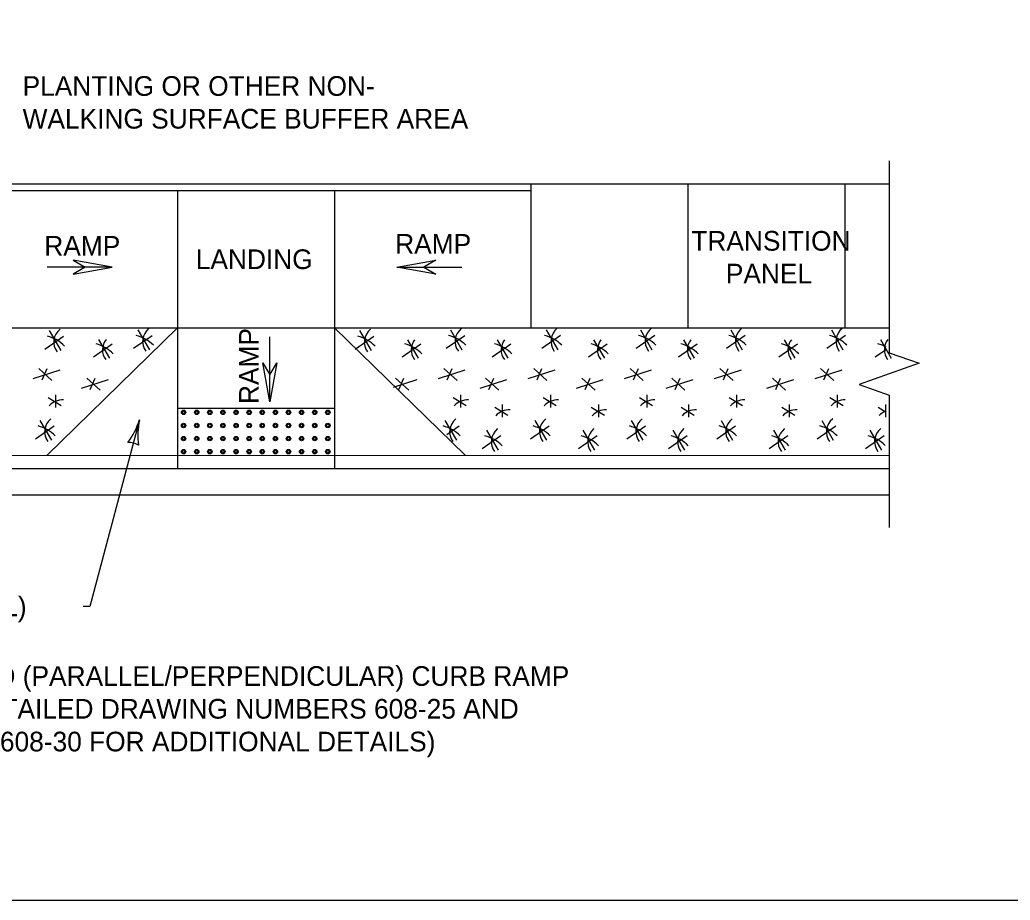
# Model space of a CAD drawing. Extents: x 49991.4 to 50021, y 49987.6 to 50011.4.
# Drawn here: x 50011.508 to 50014.53, y 49999.886 to 50002.573 of the extents above; entities that cross this region are included whole.
import ezdxf

# ---------------------------------------------------------------- set-up
doc = ezdxf.new("R2010")
doc.units = 0
for name, color, linetype in [('Level 1', 7, 'Continuous'), ('Level 2', 7, 'Continuous'), ('Level 3', 7, 'Continuous'), ('Level 6', 7, 'Continuous')]:
    doc.layers.add(name, color=color, linetype=linetype)

msp = doc.modelspace()

# ---------------------------------------------------------------- linework, layer by layer
at = {"layer": 'Level 1'}
for p, q in [((50010.2316, 50002.0716), (50014.16, 50002.0715)), ((50013.0671, 50002.0715), (50013.067, 50001.6325)), ((50013.5463, 50002.0714), (50013.5461, 50001.6326)), ((50014.0255, 50002.0712), (50014.0253, 50001.6324)), ((50011.3901, 50002.0515), (50013.0671, 50002.0516)), ((50011.9889, 50002.0515), (50011.989, 50001.2031)), ((50012.4681, 50002.0515), (50012.4682, 50001.2031)), ((50010.2317, 50001.6321), (50014.16, 50001.6325)), ((50011.5841, 50001.5677), (50011.6411, 50001.6073)), ((50011.989, 50001.6323), (50011.59, 50001.2432)), ((50011.5974, 50001.6241), (50011.6327, 50001.5631)), ((50011.6154, 50001.6323), (50011.6155, 50001.6321)), ((50011.6261, 50001.6321), (50011.6263, 50001.6323)), ((50011.8551, 50001.57), (50011.9121, 50001.6096)), ((50011.8685, 50001.6264), (50011.9037, 50001.5654)), ((50011.9094, 50001.6323), (50011.9095, 50001.6321)), ((50011.9201, 50001.6321), (50011.9203, 50001.6323)), ((50012.4682, 50001.6323), (50012.867, 50001.2434)), ((50012.5313, 50001.5675), (50012.5884, 50001.6071)), ((50012.5447, 50001.6239), (50012.58, 50001.5629)), ((50012.8083, 50001.57), (50012.8653, 50001.6096)), ((50012.8216, 50001.6264), (50012.8569, 50001.5654)), ((50013.101, 50001.5702), (50013.158, 50001.6098)), ((50013.1143, 50001.6265), (50013.1496, 50001.5656)), ((50013.3881, 50001.5702), (50013.4451, 50001.6098)), ((50013.4014, 50001.6265), (50013.4367, 50001.5656)), ((50013.6637, 50001.5702), (50013.7207, 50001.6098)), ((50013.677, 50001.6265), (50013.7123, 50001.5656)), ((50013.9706, 50001.5702), (50014.0276, 50001.6098)), ((50013.9839, 50001.6265), (50014.0192, 50001.5656)), ((50011.7326, 50001.5443), (50011.7897, 50001.5839)), ((50011.7481, 50001.5969), (50011.7812, 50001.5396)), ((50012.6744, 50001.5443), (50012.7315, 50001.5839)), ((50012.6903, 50001.5963), (50012.7231, 50001.5396)), ((50012.9487, 50001.5443), (50013.0058, 50001.5839)), ((50012.9646, 50001.5963), (50012.9974, 50001.5396)), ((50013.2427, 50001.5443), (50013.2998, 50001.5839)), ((50013.2586, 50001.5963), (50013.2914, 50001.5396)), ((50013.5171, 50001.5443), (50013.5741, 50001.5839)), ((50013.5329, 50001.5963), (50013.5657, 50001.5396)), ((50013.824, 50001.5443), (50013.881, 50001.5839)), ((50013.8398, 50001.5963), (50013.8726, 50001.5396)), ((50014.1338, 50001.5964), (50014.1666, 50001.5397)), ((50014.118, 50001.5444), (50014.1518, 50001.5678)), ((50011.5491, 50001.4783), (50011.6312, 50001.5043)), ((50011.6061, 50001.4722), (50011.5658, 50001.5088)), ((50011.5759, 50001.4738), (50011.591, 50001.5088)), ((50012.7849, 50001.4783), (50012.867, 50001.5043)), ((50012.8419, 50001.4722), (50012.8016, 50001.5088)), ((50012.8117, 50001.4738), (50012.8268, 50001.5088)), ((50013.0592, 50001.4783), (50013.1414, 50001.5043)), ((50013.1162, 50001.4722), (50013.0759, 50001.5088)), ((50013.0861, 50001.4738), (50013.1011, 50001.5088)), ((50013.3532, 50001.4783), (50013.4354, 50001.5043)), ((50013.4102, 50001.4722), (50013.3699, 50001.5088)), ((50013.3801, 50001.4738), (50013.3951, 50001.5088)), ((50013.6275, 50001.4783), (50013.7097, 50001.5043)), ((50013.6846, 50001.4722), (50013.6442, 50001.5088)), ((50013.6544, 50001.4738), (50013.6695, 50001.5088)), ((50013.9344, 50001.4783), (50014.0166, 50001.5043)), ((50013.9915, 50001.4722), (50013.9511, 50001.5088)), ((50013.9613, 50001.4738), (50013.9764, 50001.5088)), ((50011.6959, 50001.4483), (50011.7781, 50001.4743)), ((50011.753, 50001.4422), (50011.7126, 50001.4788)), ((50011.7228, 50001.4438), (50011.7379, 50001.4788)), ((50012.6485, 50001.4517), (50012.7199, 50001.4743)), ((50012.6948, 50001.4422), (50012.6544, 50001.4788)), ((50012.6646, 50001.4438), (50012.6797, 50001.4788)), ((50012.9121, 50001.4483), (50012.9942, 50001.4743)), ((50012.9691, 50001.4422), (50012.9288, 50001.4788)), ((50012.9389, 50001.4438), (50012.954, 50001.4788)), ((50013.2061, 50001.4483), (50013.2882, 50001.4743)), ((50013.2631, 50001.4422), (50013.2228, 50001.4788)), ((50013.2329, 50001.4438), (50013.248, 50001.4788)), ((50013.4804, 50001.4483), (50013.5626, 50001.4743)), ((50013.5374, 50001.4422), (50013.4971, 50001.4788)), ((50013.5072, 50001.4438), (50013.5223, 50001.4788)), ((50013.7873, 50001.4483), (50013.8695, 50001.4743)), ((50013.8443, 50001.4422), (50013.804, 50001.4788)), ((50013.8141, 50001.4438), (50013.8292, 50001.4788)), ((50014.1232, 50001.4787), (50014.1232, 50001.4789)), ((50011.6175, 50001.3898), (50011.6175, 50001.428)), ((50012.8534, 50001.3898), (50012.8534, 50001.428)), ((50013.1277, 50001.3898), (50013.1277, 50001.428)), ((50013.4217, 50001.3898), (50013.4217, 50001.428)), ((50013.696, 50001.3898), (50013.696, 50001.428)), ((50014.0029, 50001.3898), (50014.0029, 50001.428)), ((50011.5942, 50001.4203), (50011.6344, 50001.3959)), ((50012.83, 50001.4203), (50012.8702, 50001.3959)), ((50012.9805, 50001.3598), (50012.9805, 50001.398)), ((50013.1043, 50001.4203), (50013.1445, 50001.3959)), ((50013.2745, 50001.3598), (50013.2745, 50001.398)), ((50013.3983, 50001.4203), (50013.4385, 50001.3959)), ((50013.5489, 50001.3598), (50013.5489, 50001.398)), ((50013.6726, 50001.4203), (50013.7128, 50001.3959)), ((50013.8558, 50001.3598), (50013.8558, 50001.398)), ((50013.9795, 50001.4203), (50014.0197, 50001.3959)), ((50014.1498, 50001.3599), (50014.1498, 50001.3981)), ((50011.989, 50001.3872), (50012.4682, 50001.3873)), ((50012.9572, 50001.3903), (50012.9974, 50001.3659)), ((50013.2512, 50001.3903), (50013.2914, 50001.3659)), ((50013.5255, 50001.3903), (50013.5657, 50001.3659)), ((50013.8324, 50001.3903), (50013.8726, 50001.3659)), ((50014.1264, 50001.3904), (50014.1515, 50001.3752)), ((50011.5691, 50001.3501), (50011.6044, 50001.2892)), ((50012.8049, 50001.3501), (50012.8402, 50001.2892)), ((50013.0792, 50001.3501), (50013.1145, 50001.2892)), ((50013.3732, 50001.3501), (50013.4085, 50001.2892)), ((50013.6476, 50001.3501), (50013.6828, 50001.2892)), ((50013.9545, 50001.3501), (50013.9897, 50001.2892)), ((50011.5557, 50001.2938), (50011.6128, 50001.3334)), ((50012.8108, 50001.3071), (50012.8486, 50001.3334)), ((50012.9321, 50001.3201), (50012.9674, 50001.2592)), ((50013.0659, 50001.2938), (50013.1229, 50001.3334)), ((50013.2261, 50001.3201), (50013.2614, 50001.2592)), ((50013.3599, 50001.2938), (50013.4169, 50001.3334)), ((50013.5004, 50001.3201), (50013.5357, 50001.2592)), ((50013.6342, 50001.2938), (50013.6912, 50001.3334)), ((50013.8073, 50001.3201), (50013.8426, 50001.2592)), ((50013.9411, 50001.2938), (50013.9981, 50001.3334)), ((50014.1013, 50001.3202), (50014.1366, 50001.2593)), ((50012.9187, 50001.2638), (50012.9758, 50001.3034)), ((50013.2127, 50001.2638), (50013.2698, 50001.3034)), ((50013.4871, 50001.2638), (50013.5441, 50001.3034)), ((50013.794, 50001.2638), (50013.851, 50001.3034)), ((50014.088, 50001.2639), (50014.145, 50001.3035)), ((50010.2316, 50001.243), (50014.16, 50001.2435)), ((50010.2316, 50001.2033), (50014.16, 50001.2029)), ((50010.2316, 50001.1232), (50014.16, 50001.1232))]:
    msp.add_line(p, q, dxfattribs=at)
msp.add_lwpolyline([(50020.9378, 50008.1646), (50009.7374, 50008.1646), (50009.7374, 49999.8856), (50020.9378, 49999.8856)], close=True, dxfattribs=at)
msp.add_lwpolyline([(50020.9378, 50008.1646), (50009.7374, 50008.1646), (50009.7374, 49999.8856), (50020.9378, 49999.8856)], close=True, dxfattribs=at)
for centre, radius in [((50012.0077, 50001.3745), 0.00675), ((50012.0077, 50001.3745), 0.00375), ((50012.0477, 50001.3745), 0.00675), ((50012.0477, 50001.3745), 0.00375), ((50012.0877, 50001.3745), 0.00675), ((50012.0877, 50001.3745), 0.00375), ((50012.1277, 50001.3745), 0.00675), ((50012.1277, 50001.3745), 0.00375), ((50012.1677, 50001.3745), 0.00675), ((50012.1677, 50001.3745), 0.00375), ((50012.2077, 50001.3745), 0.00675), ((50012.2077, 50001.3745), 0.00375), ((50012.2477, 50001.3745), 0.00675), ((50012.2477, 50001.3745), 0.00375), ((50012.2877, 50001.3745), 0.00675), ((50012.2877, 50001.3745), 0.00375), ((50012.3277, 50001.3745), 0.00675), ((50012.3277, 50001.3745), 0.00375), ((50012.3677, 50001.3745), 0.00675), ((50012.3677, 50001.3745), 0.00375), ((50012.4077, 50001.3745), 0.00675), ((50012.4077, 50001.3745), 0.00375), ((50012.4477, 50001.3745), 0.00675), ((50012.4477, 50001.3745), 0.00375), ((50012.0077, 50001.3345), 0.00675), ((50012.0077, 50001.3345), 0.00375), ((50012.0477, 50001.3345), 0.00675), ((50012.0477, 50001.3345), 0.00375), ((50012.0877, 50001.3345), 0.00675), ((50012.0877, 50001.3345), 0.00375), ((50012.1277, 50001.3345), 0.00675), ((50012.1277, 50001.3345), 0.00375), ((50012.1677, 50001.3345), 0.00675), ((50012.1677, 50001.3345), 0.00375), ((50012.2077, 50001.3345), 0.00675), ((50012.2077, 50001.3345), 0.00375), ((50012.2477, 50001.3345), 0.00675), ((50012.2477, 50001.3345), 0.00375), ((50012.2877, 50001.3345), 0.00675), ((50012.2877, 50001.3345), 0.00375), ((50012.3277, 50001.3345), 0.00675), ((50012.3277, 50001.3345), 0.00375), ((50012.3677, 50001.3345), 0.00675), ((50012.3677, 50001.3345), 0.00375), ((50012.4077, 50001.3345), 0.00675), ((50012.4077, 50001.3345), 0.00375), ((50012.4477, 50001.3345), 0.00675), ((50012.4477, 50001.3345), 0.00375), ((50012.0077, 50001.2945), 0.00675), ((50012.0077, 50001.2945), 0.00375), ((50012.0477, 50001.2945), 0.00675), ((50012.0477, 50001.2945), 0.00375), ((50012.0877, 50001.2945), 0.00675), ((50012.0877, 50001.2945), 0.00375), ((50012.1277, 50001.2945), 0.00675), ((50012.1277, 50001.2945), 0.00375), ((50012.1677, 50001.2945), 0.00675), ((50012.1677, 50001.2945), 0.00375), ((50012.2077, 50001.2945), 0.00675), ((50012.2077, 50001.2945), 0.00375), ((50012.2477, 50001.2945), 0.00675), ((50012.2477, 50001.2945), 0.00375), ((50012.2877, 50001.2945), 0.00675), ((50012.2877, 50001.2945), 0.00375), ((50012.3277, 50001.2945), 0.00675), ((50012.3277, 50001.2945), 0.00375), ((50012.3677, 50001.2945), 0.00675), ((50012.3677, 50001.2945), 0.00375), ((50012.4077, 50001.2945), 0.00675), ((50012.4077, 50001.2945), 0.00375), ((50012.4477, 50001.2945), 0.00675), ((50012.4477, 50001.2945), 0.00375), ((50012.0077, 50001.2545), 0.00675), ((50012.0077, 50001.2545), 0.00375), ((50012.0477, 50001.2545), 0.00675), ((50012.0477, 50001.2545), 0.00375), ((50012.0877, 50001.2545), 0.00675), ((50012.0877, 50001.2545), 0.00375), ((50012.1277, 50001.2545), 0.00675), ((50012.1277, 50001.2545), 0.00375), ((50012.1677, 50001.2545), 0.00675), ((50012.1677, 50001.2545), 0.00375), ((50012.2077, 50001.2545), 0.00675), ((50012.2077, 50001.2545), 0.00375), ((50012.2477, 50001.2545), 0.00675), ((50012.2477, 50001.2545), 0.00375), ((50012.2877, 50001.2545), 0.00675), ((50012.2877, 50001.2545), 0.00375), ((50012.3277, 50001.2545), 0.00675), ((50012.3277, 50001.2545), 0.00375), ((50012.3677, 50001.2545), 0.00675), ((50012.3677, 50001.2545), 0.00375), ((50012.4077, 50001.2545), 0.00675), ((50012.4077, 50001.2545), 0.00375), ((50012.4477, 50001.2545), 0.00675), ((50012.4477, 50001.2545), 0.00375)]:
    msp.add_circle(centre, radius, dxfattribs=at)
for centre, major_axis, start_param, end_param in [((50011.6708, 50001.589), (-0.0591, 0), 5.450961, 6.875887), ((50011.6725, 50001.6255), (-0.0591, 0), 6.155919, 6.158231), ((50011.5651, 50001.5492), (0.1074, 0), 1.015046, 1.017455), ((50011.8193, 50001.5955), (-0.0591, 0), 5.527296, 5.530814), ((50011.8344, 50001.5151), (0.1074, 0), 0.715682, 1.301104), ((50011.9418, 50001.5913), (-0.0591, 0), 5.450961, 6.875887), ((50011.9665, 50001.6255), (-0.0591, 0), 6.155426, 6.158231), ((50011.8591, 50001.5492), (0.1074, 0), 1.015046, 1.017966), ((50012.6181, 50001.5889), (-0.0591, 0), 5.450961, 6.875887), ((50012.7876, 50001.5151), (0.1074, 0), 0.715682, 1.301104), ((50012.895, 50001.5913), (-0.0591, 0), 5.450961, 6.875887), ((50013.0803, 50001.5152), (0.1074, 0), 0.715682, 1.301104), ((50013.1877, 50001.5915), (-0.0591, 0), 5.450961, 6.875887), ((50013.3674, 50001.5152), (0.1074, 0), 0.715682, 1.301104), ((50013.4748, 50001.5915), (-0.0591, 0), 5.450961, 6.875887), ((50013.643, 50001.5152), (0.1074, 0), 0.715682, 1.301104), ((50013.7504, 50001.5915), (-0.0591, 0), 5.450961, 6.875887), ((50013.9499, 50001.5152), (0.1074, 0), 0.715682, 1.301104), ((50014.0573, 50001.5915), (-0.0591, 0), 5.450961, 6.875887), ((50011.5634, 50001.5128), (0.1074, 0), 0.715682, 1.301104), ((50011.712, 50001.4893), (0.1074, 0), 0.715682, 1.301104), ((50011.8193, 50001.5656), (-0.0591, 0), 5.660038, 6.875887), ((50012.5107, 50001.5126), (0.1074, 0), 0.715682, 1.301104), ((50012.6538, 50001.4893), (0.1074, 0), 0.715682, 1.301104), ((50012.7611, 50001.5656), (-0.0591, 0), 5.673488, 6.875887), ((50012.9281, 50001.4893), (0.1074, 0), 0.715682, 1.301104), ((50013.0355, 50001.5656), (-0.0591, 0), 5.673488, 6.875887), ((50013.2221, 50001.4893), (0.1074, 0), 0.715682, 1.301104), ((50013.3295, 50001.5656), (-0.0591, 0), 5.673488, 6.875887), ((50013.4964, 50001.4893), (0.1074, 0), 0.715682, 1.301104), ((50013.6038, 50001.5656), (-0.0591, 0), 5.673488, 6.875887), ((50013.8033, 50001.4893), (0.1074, 0), 0.715682, 1.301104), ((50013.9107, 50001.5656), (-0.0591, 0), 5.673488, 6.875887), ((50014.0973, 50001.4894), (0.1074, 0), 1.043909, 1.301104), ((50014.2047, 50001.5657), (-0.0591, 0), 5.673488, 6.875887), ((50011.6411, 50001.3606), (-0.0573, 0), 4.712389, 5.577205), ((50012.8769, 50001.3606), (-0.0573, 0), 4.712389, 5.577205), ((50013.1512, 50001.3606), (-0.0573, 0), 4.712389, 5.577205), ((50013.4452, 50001.3606), (-0.0573, 0), 4.712389, 5.577205), ((50013.7196, 50001.3606), (-0.0573, 0), 4.712389, 5.577205), ((50014.0265, 50001.3606), (-0.0573, 0), 4.712389, 5.577205), ((50013.0041, 50001.3306), (-0.0573, 0), 4.712389, 5.577205), ((50013.2981, 50001.3306), (-0.0573, 0), 4.712389, 5.577205), ((50013.5724, 50001.3306), (-0.0573, 0), 4.712389, 5.577205), ((50013.8793, 50001.3306), (-0.0573, 0), 4.712389, 5.577205), ((50014.1733, 50001.3307), (-0.0573, 0), 5.123504, 5.577205), ((50011.6425, 50001.3151), (-0.0591, 0), 5.450961, 6.875887), ((50012.8783, 50001.3151), (-0.0591, 0), 5.450961, 6.875887), ((50013.1526, 50001.3151), (-0.0591, 0), 5.450961, 6.875887), ((50013.4466, 50001.3151), (-0.0591, 0), 5.450961, 6.875887), ((50013.7209, 50001.3151), (-0.0591, 0), 5.450961, 6.875887), ((50014.0278, 50001.3151), (-0.0591, 0), 5.450961, 6.875887), ((50011.5351, 50001.2388), (0.1074, 0), 0.715682, 1.301104), ((50012.7709, 50001.2388), (0.1074, 0), 0.715682, 1.301104), ((50013.0055, 50001.2851), (-0.0591, 0), 5.450961, 6.875887), ((50013.0452, 50001.2388), (0.1074, 0), 0.715682, 1.301104), ((50013.2995, 50001.2851), (-0.0591, 0), 5.450961, 6.875887), ((50013.3392, 50001.2388), (0.1074, 0), 0.715682, 1.301104), ((50013.5738, 50001.2851), (-0.0591, 0), 5.450961, 6.875887), ((50013.6135, 50001.2388), (0.1074, 0), 0.715682, 1.301104), ((50013.8807, 50001.2851), (-0.0591, 0), 5.450961, 6.875887), ((50013.9204, 50001.2388), (0.1074, 0), 0.715682, 1.301104), ((50014.1747, 50001.2852), (-0.0591, 0), 5.450961, 6.875887), ((50012.8981, 50001.2088), (0.1074, 0), 0.715682, 1.301104), ((50013.1921, 50001.2088), (0.1074, 0), 0.715682, 1.301104), ((50013.4664, 50001.2088), (0.1074, 0), 0.715682, 1.301104), ((50013.7733, 50001.2088), (0.1074, 0), 0.715682, 1.301104), ((50014.0673, 50001.2089), (0.1074, 0), 0.715682, 1.301104)]:
    msp.add_ellipse(centre, major_axis=major_axis, ratio=0.909091, start_param=start_param, end_param=end_param, dxfattribs=at)
at = {"layer": 'Level 3'}
for p, q in [((50011.7902, 50001.8175), (50011.5916, 50001.8175)), ((50012.6583, 50001.8175), (50012.857, 50001.8175)), ((50012.2709, 50001.4065), (50012.2709, 50001.6052)), ((50011.8732, 50001.3517), (50011.722, 50000.782)), ((50011.722, 50000.782), (50011.7016, 50000.782))]:
    msp.add_line(p, q, dxfattribs=at)
for points in [[(50011.6711, 50001.7967), (50011.7902, 50001.8175), (50011.6711, 50001.8387), (50011.7074, 50001.8176)], [(50012.7774, 50001.7967), (50012.6583, 50001.8175), (50012.7774, 50001.8387), (50012.7411, 50001.8176)], [(50012.2917, 50001.5257), (50012.2709, 50001.4065), (50012.2496, 50001.5257), (50012.2707, 50001.4893)]]:
    msp.add_lwpolyline(points, close=True, dxfattribs=at)
for centre, radius, start, end in [((50011.6608, 50001.4176), 0.2223, 322.5901, 342.7736), ((50012.1011, 50001.3032), 0.233, 167.9614, 187.2112), ((50011.8403, 50001.2278), 0.0548, 57.2729, 92.9952)]:
    msp.add_arc(centre, radius, start, end, dxfattribs=at)
at = {"layer": 'Level 6'}
for p, q in [((50014.16, 50002.1417), (50014.16, 50001.5566)), ((50014.16, 50001.5566), (50014.2514, 50001.5242)), ((50014.2514, 50001.5242), (50014.16, 50001.4918)), ((50014.16, 50001.4918), (50014.0686, 50001.4594)), ((50014.0686, 50001.4594), (50014.16, 50001.427)), ((50014.16, 50001.427), (50014.16, 50001.0233))]:
    msp.add_line(p, q, dxfattribs=at)

# ---------------------------------------------------------------- texts
at = {"layer": 'Level 2'}
for s, p in [('PLANTING OR OTHER NON-', (50011.5165, 50002.3406)), ('WALKING SURFACE BUFFER AREA', (50011.5165, 50002.2406)), ('RAMP', (50011.5827, 50001.8528)), ('RAMP', (50012.6533, 50001.8588)), ('TRANSITION', (50013.5567, 50001.868)), ('LANDING', (50012.0449, 50001.8119)), ('PANEL ', (50013.6621, 50001.768)), ('OR BUFFER AREA MATERIAL)', (50010.3741, 50000.752)), ('COMBINED (PARALLEL/PERPENDICULAR) CURB RAMP', (50011.0622, 50000.5398)), ('(SEE DETAILED DRAWING NUMBERS 608-25 AND', (50011.1309, 50000.4398)), ('608-30 FOR ADDITIONAL DETAILS)', (50011.4473, 50000.3398))]:
    msp.add_text(s, height=0.06, dxfattribs=at).set_placement(p)
msp.add_text('RAMP', height=0.06, rotation=90, dxfattribs=at).set_placement((50012.237, 50001.4))

doc.saveas('drawing.dxf')
